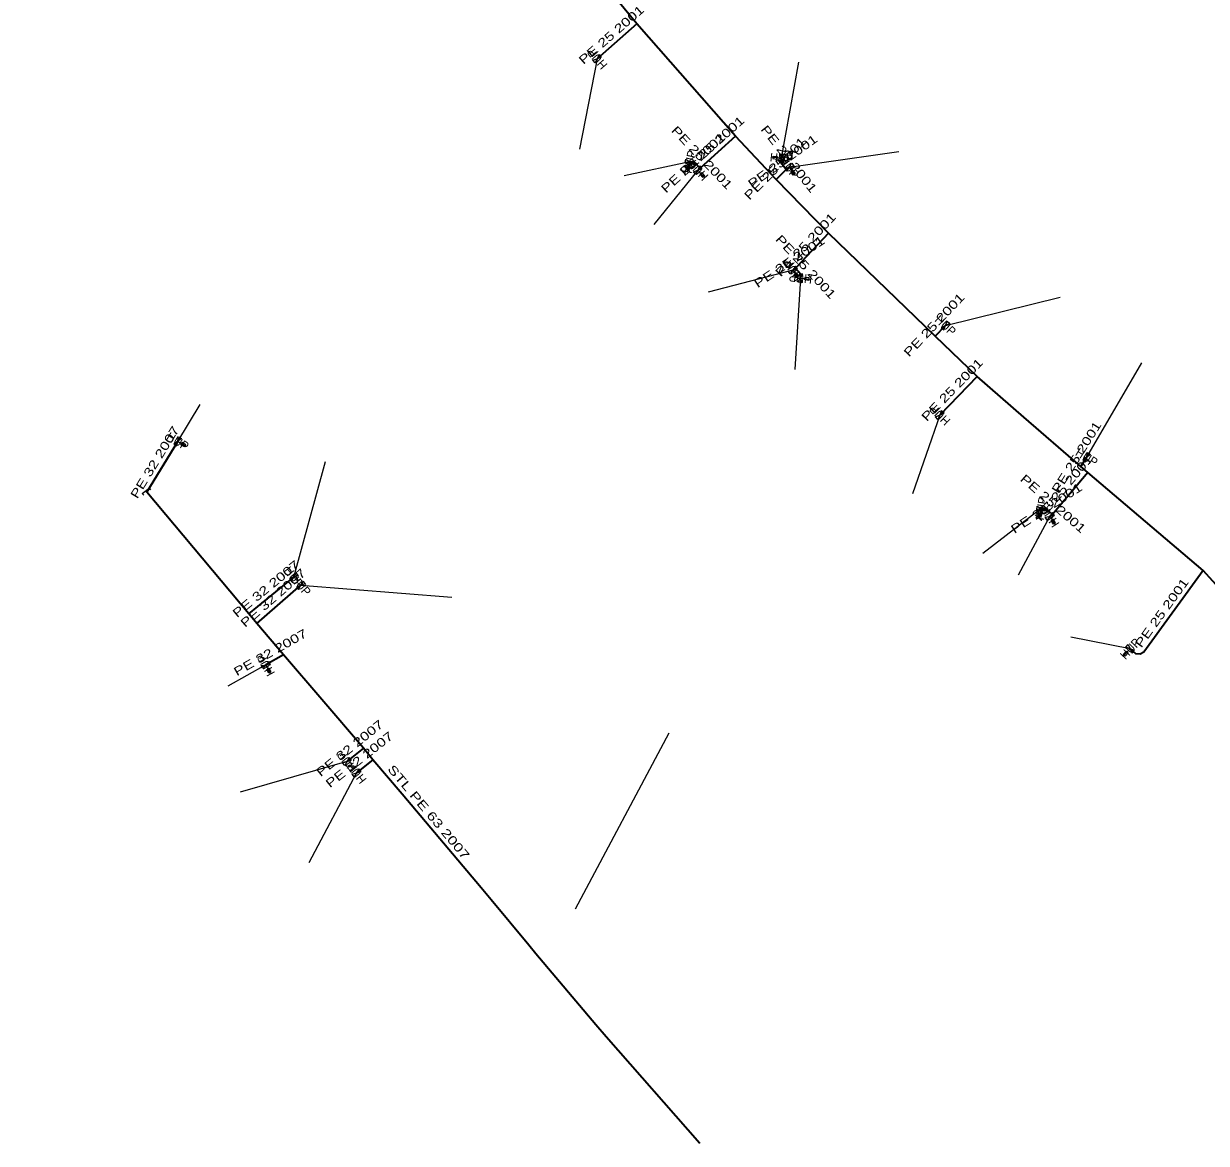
# Model space of a CAD drawing. Extents: x -737484 to -734496, y -1033882 to -1030666.
# Drawn here: x -735115.3 to -734978.9, y -1033712.1 to -1033583 of the extents above; entities that cross this region are included whole.
import ezdxf
from ezdxf.enums import TextEntityAlignment as Align

# ---------------------------------------------------------------- set-up
doc = ezdxf.new("R2010")
doc.units = 0
doc.header["$LTSCALE"] = 0.4
for name, color, linetype, lineweight in [('1', 7, 'Continuous', 13), ('22', 7, 'Continuous', 25), ('5', 7, 'Continuous', 35), ('7', 7, 'Continuous', 35)]:
    doc.layers.add(name, color=color, linetype=linetype, lineweight=lineweight)
doc.layers.add('2', color=7, linetype='Continuous')

msp = doc.modelspace()

# ---------------------------------------------------------------- linework, layer by layer
at = {"layer": '1'}
for p, q in [((-735028.484, -1033598.355), (-735028.832, -1033598.318)), ((-735027.92, -1033598.49), (-735028.417, -1033598.437)), ((-735038.692, -1033599.446), (-735038.765, -1033599.789)), ((-735038.5, -1033598.9), (-735038.603, -1033599.389)), ((-735037.55, -1033599.86), (-735037.215, -1033600.231)), ((-735027.03, -1033599.53), (-735026.736, -1033599.934)), ((-735037.22, -1033600.337), (-735036.986, -1033600.597)), ((-735026.752, -1033600.039), (-735026.546, -1033600.322)), ((-735026.62, -1033611.38), (-735026.34, -1033611.794)), ((-735026.36, -1033611.898), (-735026.164, -1033612.188)), ((-735025.73, -1033612.32), (-735025.232, -1033612.372)), ((-735025.165, -1033612.454), (-735024.817, -1033612.491)), ((-735097.525, -1033631.14), (-735097.096, -1033631.397)), ((-735097.07, -1033631.5), (-735096.77, -1033631.68)), ((-734997.98, -1033638.87), (-734998.058, -1033639.363)), ((-734998.144, -1033639.426), (-734998.198, -1033639.771)), ((-734996.99, -1033639.78), (-734996.717, -1033640.199)), ((-734996.739, -1033640.303), (-734996.549, -1033640.596)), ((-734988.167, -1033655.429), (-734988.405, -1033655.685)), ((-734987.72, -1033655.06), (-734988.06, -1033655.425)), ((-735087.373, -1033656.928), (-735087.13, -1033657.365)), ((-735087.159, -1033657.467), (-735086.99, -1033657.773))]:
    msp.add_line(p, q, dxfattribs=at)
for points in [[(-735049.416, -1033587.487), (-735049.678, -1033587.186), (-735048.661, -1033586.831), (-735048.923, -1033586.53)], [(-735028.914, -1033598.385), (-735028.93, -1033598.534), (-735028.432, -1033598.586), (-735028.417, -1033598.437)], [(-735028.914, -1033598.385), (-735028.898, -1033598.236), (-735028.401, -1033598.288), (-735028.417, -1033598.437)], [(-735028.872, -1033598.352), (-735028.865, -1033598.278), (-735028.442, -1033598.322), (-735028.45, -1033598.397)], [(-735028.066, -1033597.97), (-735027.668, -1033598.012), (-735028.171, -1033598.965), (-735027.773, -1033599.007)], [(-735039.03, -1033598.99), (-735038.947, -1033598.599), (-735038.052, -1033599.198), (-735037.969, -1033598.807)], [(-735038.707, -1033599.878), (-735038.854, -1033599.846), (-735038.75, -1033599.357), (-735038.603, -1033599.389)], [(-735038.736, -1033599.833), (-735038.809, -1033599.817), (-735038.721, -1033599.401), (-735038.647, -1033599.417)], [(-735038.707, -1033599.878), (-735038.561, -1033599.909), (-735038.457, -1033599.42), (-735038.603, -1033599.389)], [(-735037.778, -1033600.347), (-735038.051, -1033600.054), (-735037.046, -1033599.665), (-735037.319, -1033599.372)], [(-735026.743, -1033599.073), (-735026.507, -1033599.396), (-735027.552, -1033599.661), (-735027.316, -1033599.984)], [(-735026.442, -1033600.339), (-735026.32, -1033600.25), (-735026.614, -1033599.846), (-735026.736, -1033599.934)], [(-735036.88, -1033600.603), (-735036.992, -1033600.703), (-735037.326, -1033600.331), (-735037.215, -1033600.231)], [(-735036.933, -1033600.599), (-735036.989, -1033600.649), (-735037.273, -1033600.334), (-735037.218, -1033600.283)], [(-735036.88, -1033600.603), (-735036.769, -1033600.502), (-735037.103, -1033600.131), (-735037.215, -1033600.231)], [(-735026.442, -1033600.339), (-735026.563, -1033600.427), (-735026.857, -1033600.022), (-735026.736, -1033599.934)], [(-735026.494, -1033600.33), (-735026.555, -1033600.374), (-735026.804, -1033600.03), (-735026.744, -1033599.986)], [(-735026.921, -1033611.825), (-735027.145, -1033611.493), (-735026.092, -1033611.266), (-735026.316, -1033610.934)], [(-735026.06, -1033612.209), (-735026.185, -1033612.292), (-735026.464, -1033611.878), (-735026.34, -1033611.794)], [(-735026.112, -1033612.198), (-735026.174, -1033612.24), (-735026.412, -1033611.887), (-735026.35, -1033611.845)], [(-735026.06, -1033612.209), (-735025.936, -1033612.125), (-735026.216, -1033611.71), (-735026.34, -1033611.794)], [(-735025.583, -1033612.837), (-735025.981, -1033612.795), (-735025.478, -1033611.842), (-735025.876, -1033611.8)], [(-735024.735, -1033612.424), (-735024.751, -1033612.573), (-735025.248, -1033612.521), (-735025.232, -1033612.372)], [(-735024.735, -1033612.424), (-735024.719, -1033612.275), (-735025.217, -1033612.223), (-735025.232, -1033612.372)], [(-735024.777, -1033612.457), (-735024.784, -1033612.531), (-735025.207, -1033612.487), (-735025.199, -1033612.412)], [(-735008.825, -1033617.267), (-735008.532, -1033617.54), (-735009.507, -1033617.999), (-735009.214, -1033618.272)], [(-735009.882, -1033628.598), (-735010.17, -1033628.32), (-735009.187, -1033627.879), (-735009.475, -1033627.601)], [(-735097.438, -1033630.608), (-735097.096, -1033630.814), (-735097.953, -1033631.465), (-735097.611, -1033631.671)], [(-735096.667, -1033631.655), (-735096.745, -1033631.783), (-735097.173, -1033631.526), (-735097.096, -1033631.397)], [(-735096.719, -1033631.667), (-735096.758, -1033631.731), (-735097.122, -1033631.512), (-735097.083, -1033631.448)], [(-735096.667, -1033631.655), (-735096.59, -1033631.526), (-735097.019, -1033631.268), (-735097.096, -1033631.397)], [(-734992.644, -1033632.439), (-734992.305, -1033632.651), (-734993.174, -1033633.288), (-734992.835, -1033633.5)], [(-734998.504, -1033638.989), (-734998.441, -1033638.594), (-734997.516, -1033639.145), (-734997.453, -1033638.75)], [(-734998.136, -1033639.857), (-734998.284, -1033639.834), (-734998.206, -1033639.34), (-734998.058, -1033639.363)], [(-734998.167, -1033639.814), (-734998.241, -1033639.802), (-734998.174, -1033639.382), (-734998.1, -1033639.394)], [(-734998.136, -1033639.857), (-734997.988, -1033639.881), (-734997.91, -1033639.387), (-734998.058, -1033639.363)], [(-734997.3, -1033640.22), (-734997.518, -1033639.884), (-734996.461, -1033639.675), (-734996.679, -1033639.339)], [(-734996.445, -1033640.618), (-734996.571, -1033640.7), (-734996.843, -1033640.281), (-734996.717, -1033640.199)], [(-734996.497, -1033640.606), (-734996.559, -1033640.647), (-734996.791, -1033640.291), (-734996.728, -1033640.25)], [(-734996.445, -1033640.618), (-734996.319, -1033640.536), (-734996.591, -1033640.117), (-734996.717, -1033640.199)], [(-735083.872, -1033646.332), (-735083.62, -1033646.643), (-735084.649, -1033646.962), (-735084.397, -1033647.273)], [(-735083.086, -1033647.252), (-735082.824, -1033647.553), (-735083.841, -1033647.908), (-735083.579, -1033648.209)], [(-734988.401, -1033655.791), (-734988.511, -1033655.689), (-734988.17, -1033655.323), (-734988.06, -1033655.425)], [(-734988.403, -1033655.738), (-734988.457, -1033655.687), (-734988.168, -1033655.376), (-734988.113, -1033655.427)], [(-734988.401, -1033655.791), (-734988.292, -1033655.893), (-734987.951, -1033655.527), (-734988.06, -1033655.425)], [(-734988.221, -1033654.865), (-734987.948, -1033654.572), (-734987.489, -1033655.547), (-734987.216, -1033655.254)], [(-735087.713, -1033657.345), (-735087.907, -1033656.995), (-735086.838, -1033656.86), (-735087.032, -1033656.51)], [(-735086.888, -1033657.802), (-735087.019, -1033657.875), (-735087.261, -1033657.438), (-735087.13, -1033657.365)], [(-735086.938, -1033657.787), (-735087.004, -1033657.823), (-735087.21, -1033657.451), (-735087.145, -1033657.415)], [(-735086.888, -1033657.802), (-735086.756, -1033657.729), (-735086.999, -1033657.292), (-735087.13, -1033657.365)], [(-735078.271, -1033668.532), (-735078.523, -1033668.221), (-735077.494, -1033667.902), (-735077.746, -1033667.591)], [(-735077.172, -1033669.834), (-735077.419, -1033669.519), (-735076.384, -1033669.218), (-735076.631, -1033668.903)]]:
    msp.add_lwpolyline(points, close=True, dxfattribs=at)
msp.add_lwpolyline([(-735101.445, -1033637.347), (-735101.602, -1033637.153), (-735100.825, -1033636.524), (-735100.668, -1033636.718)], dxfattribs=at)
at = {"layer": '22'}
for p, q in [((-735049.17, -1033587.009), (-735051.208, -1033597.452)), ((-735027.92, -1033598.489), (-735025.929, -1033587.42)), ((-735027.03, -1033599.529), (-735014.382, -1033597.719)), ((-735038.5, -1033598.899), (-735046.058, -1033600.528)), ((-735037.549, -1033599.86), (-735042.625, -1033606.145)), ((-735026.619, -1033611.38), (-735036.383, -1033613.947)), ((-735025.73, -1033612.319), (-735026.397, -1033622.842)), ((-735009.02, -1033617.77), (-734995.815, -1033614.506)), ((-734992.74, -1033632.97), (-734986.392, -1033622.073)), ((-735097.525, -1033631.14), (-735094.924, -1033626.87)), ((-735009.679, -1033628.1), (-735012.821, -1033637.198)), ((-735084.135, -1033646.803), (-735080.486, -1033633.472)), ((-734997.979, -1033638.87), (-735004.707, -1033644.063)), ((-734996.99, -1033639.78), (-735000.65, -1033646.56)), ((-735083.333, -1033647.731), (-735065.918, -1033649.111)), ((-734987.719, -1033655.06), (-734994.564, -1033653.738)), ((-735087.373, -1033656.928), (-735091.725, -1033659.389)), ((-735051.651, -1033685.056), (-735040.853, -1033664.749)), ((-735078.009, -1033668.062), (-735090.34, -1033671.605)), ((-735076.902, -1033669.369), (-735082.414, -1033679.745))]:
    msp.add_line(p, q, dxfattribs=at)
at = {"layer": '5'}
for points in [[(-734975.96, -1033649.73), (-734979.32, -1033646.03), (-734992.6, -1033634.72), (-734993.41, -1033634.04), (-735000, -1033628.33), (-735005.38, -1033623.67), (-735010.2, -1033619.02), (-735022.51, -1033607.11), (-735028.53, -1033600.95), (-735033.22, -1033595.96), (-735044.58, -1033582.99), (-735050.8, -1033575.47), (-735058.43, -1033565.92), (-735069.17, -1033552.53), (-735072.33, -1033548.15), (-735079.7, -1033538.4), (-735088.3, -1033526.83), (-735092.52, -1033520.93), (-735101.55, -1033507.83), (-735102.19, -1033506.8), (-735114.06, -1033488.95), (-735115.28, -1033487.08)], [(-735037.336, -1033712.097), (-735048.119, -1033699.823), (-735049.321, -1033698.433), (-735056.246, -1033690.224), (-735057.064, -1033689.223), (-735061.391, -1033684.007), (-735062.554, -1033682.622), (-735071.651, -1033671.827), (-735075.022, -1033667.885), (-735076.118, -1033666.539), (-735080.898, -1033660.914), (-735085.334, -1033655.775), (-735088.4, -1033652.147), (-735089.31, -1033651.046), (-735101.09, -1033636.993), (-735101.214, -1033636.839)]]:
    msp.add_lwpolyline(points, dxfattribs=at)
at = {"layer": '7'}
for p, q in [((-735044.58, -1033582.99), (-735049.17, -1033587.009)), ((-735033.22, -1033595.96), (-735037.31, -1033599.64)), ((-735037.31, -1033599.64), (-735037.549, -1033599.86)), ((-735028.53, -1033600.95), (-735027.38, -1033599.78)), ((-735027.38, -1033599.78), (-735027.03, -1033599.529)), ((-735022.51, -1033607.11), (-735026.32, -1033611.18)), ((-735026.32, -1033611.18), (-735026.619, -1033611.38)), ((-735010.2, -1033619.02), (-735009.02, -1033617.77)), ((-735005.38, -1033623.67), (-735009.679, -1033628.1)), ((-735101.09, -1033636.993), (-735097.525, -1033631.14)), ((-734993.41, -1033634.04), (-734992.74, -1033632.97)), ((-734992.6, -1033634.72), (-734996.68, -1033639.58)), ((-734996.68, -1033639.58), (-734996.99, -1033639.78)), ((-735089.31, -1033651.046), (-735084.135, -1033646.803)), ((-735088.4, -1033652.147), (-735083.333, -1033647.731)), ((-735085.334, -1033655.775), (-735087.373, -1033656.928)), ((-735076.118, -1033666.539), (-735078.009, -1033668.062)), ((-735075.022, -1033667.885), (-735076.902, -1033669.369))]:
    msp.add_line(p, q, dxfattribs=at)
for points in [[(-735027.38, -1033599.78), (-735027.98, -1033599.02), (-735027.92, -1033598.489)], [(-735037.31, -1033599.64), (-735037.89, -1033599.03), (-735038.5, -1033598.899)], [(-735026.32, -1033611.18), (-735025.68, -1033611.87), (-735025.73, -1033612.319)], [(-734996.68, -1033639.58), (-734997.38, -1033638.97), (-734997.979, -1033638.87)], [(-734979.32, -1033646.03), (-734986.14, -1033655.46), (-734986.57, -1033655.67), (-734987.09, -1033655.64), (-734987.719, -1033655.06)]]:
    msp.add_lwpolyline(points, dxfattribs=at)

# ---------------------------------------------------------------- texts
at = {"layer": '2', "width": 0.95}
for rotation, p in [(131, (-735048.7926, -1033586.6805)), (78, (-735038.0102, -1033599.0025)), (354, (-735027.9718, -1033598.9857)), (306, (-735027.434, -1033599.8226)), (133, (-735037.183, -1033599.5185)), (124, (-735026.2039, -1033611.1001)), (174, (-735025.6772, -1033611.8213)), (317, (-735009.3605, -1033618.135)), (136, (-735009.3312, -1033627.7396)), (329, (-735097.782, -1033631.5682)), (328, (-734993.0045, -1033633.3933)), (81, (-734997.4845, -1033638.9477)), (123, (-734996.5709, -1033639.5068)), (309, (-735084.5232, -1033647.1168)), (311, (-735083.7094, -1033648.0585)), (47, (-734987.353, -1033655.4005)), (119, (-735086.9351, -1033656.6849)), (129, (-735077.6198, -1033667.7472)), (128, (-735076.508, -1033669.0603))]:
    msp.add_text('HUP', height=1, rotation=rotation, dxfattribs=at).set_placement(p, align=Align.CENTER)
at = {"layer": '5', "width": 1.4}
msp.add_text('STL PE 63 2007', height=1, rotation=310.121, dxfattribs=at).set_placement((-735068.9791, -1033674.2208), align=Align.CENTER)
at = {"layer": '7', "width": 1.35}
for s, rotation, p in [('PE 25 2001', 41.205, (-735047.2039, -1033584.6233)), ('PE 25 2001', 41.979, (-735035.5989, -1033597.4274)), ('PE 25 2001', 42.63, (-735037.7681, -1033599.382)), ('PE 25 2001', 313.556, (-735037.4521, -1033598.764)), ('PE 25 2001', 308.29, (-735027.4526, -1033598.8797)), ('PE 25 2001', 45.494, (-735028.311, -1033600.0145)), ('PE 25 2001', 35.646, (-735027.4954, -1033599.2475)), ('PE 25 2001', 46.89, (-735024.7797, -1033608.8027)), ('PE 25 2001', 33.778, (-735026.747, -1033610.8639)), ('PE 25 2001', 312.847, (-735025.4796, -1033611.35)), ('PE 25 2001', 46.65, (-735009.9733, -1033618.0512)), ('PE 25 2001', 45.86, (-735007.8873, -1033625.5362)), ('PE 32 2007', 58.655, (-735099.7337, -1033633.8056)), ('PE 25 2001', 57.947, (-734993.4981, -1033633.2389)), ('PE 25 2001', 49.986, (-734995.0227, -1033636.828)), ('PE 25 2001', 318.93, (-734996.93, -1033638.6988)), ('PE 25 2001', 32.829, (-734997.1061, -1033639.2593)), ('PE 32 2007', 39.348, (-735087.039, -1033648.5374)), ('PE 32 2007', 41.073, (-735086.1945, -1033649.5623)), ('PE 25 2001', 54.125, (-734983.6778, -1033651.203)), ('PE 32 2007', 29.487, (-735086.5986, -1033655.9158)), ('PE 32 2007', 38.848, (-735077.3766, -1033666.9109)), ('PE 32 2007', 38.286, (-735076.2708, -1033668.2333))]:
    msp.add_text(s, height=1, rotation=rotation, dxfattribs=at).set_placement(p, align=Align.CENTER)

doc.saveas('drawing.dxf')
